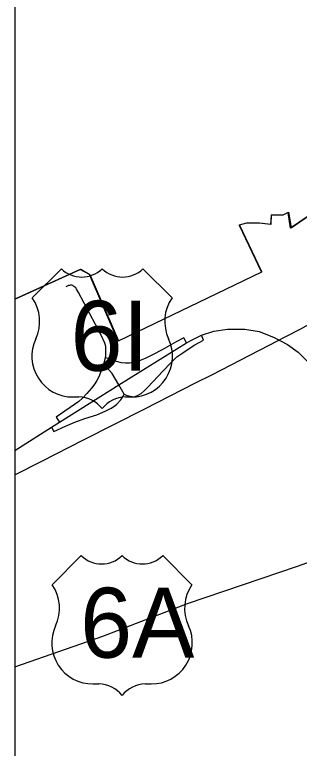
# Model space of a CAD drawing. Extents: x 0 to 96.2, y -27.5 to 31.3.
# Drawn here: x 43.823 to 44.361, y 17.525 to 18.907 of the extents above; entities that cross this region are included whole.
import ezdxf

# ---------------------------------------------------------------- set-up
doc = ezdxf.new("R2010")
doc.units = 0
for name, color, linetype in [('BOTTOM-BLKS', 7, 'Continuous'), ('TB1', 7, 'Continuous'), ('TB_PIPEMAT', 7, 'Continuous'), ('TB_PP_50x10_GRID', 7, 'Continuous'), ('TB_PROF_20x5_GRID', 7, 'Continuous'), ('TB_SIGN_XS', 7, 'Continuous'), ('TB_SUPER_50x0-5', 7, 'Continuous')]:
    doc.layers.add(name, color=color, linetype=linetype)

msp = doc.modelspace()

# ---------------------------------------------------------------- linework, layer by layer
at = {"layer": 'BOTTOM-BLKS'}
for points in [[(43.8234, 18.3711), (43.8234, 13.9869), (50.6234, 13.9869), (50.6234, 20.7869), (47.5697, 20.7869)], [(44.3788, 18.5289), (44.344, 18.5051), (44.3393, 18.5347), (44.3294, 18.5297), (44.3074, 18.5296), (44.3064, 18.5117), (44.2847, 18.5143), (44.2608, 18.5145), (44.2467, 18.5106), (44.2891, 18.4219), (44.0186, 18.2919), (43.9647, 18.4174), (43.9471, 18.4272), (43.8234, 18.3711)]]:
    msp.add_lwpolyline(points, dxfattribs=at)
at = {"layer": 'TB1'}
msp.add_line((43.8234, 20.7869), (43.8234, 13.9869), dxfattribs=at)
at = {"layer": 'TB_PIPEMAT'}
msp.add_lwpolyline([(43.8234, 18.3712), (43.948, 18.4277), (43.9655, 18.4179), (44.0195, 18.2924), (44.2899, 18.4224), (44.2476, 18.5111), (44.2616, 18.515), (44.2855, 18.5147), (44.3072, 18.5122), (44.3082, 18.5301), (44.3303, 18.5302), (44.3401, 18.5352), (44.3448, 18.5056), (44.3796, 18.5293)], dxfattribs=at)
at = {"layer": 'TB_PP_50x10_GRID'}
msp.add_lwpolyline([(43.8234, 18.04), (43.8748, 18.0658), (43.953, 18.1061), (44.0692, 18.1647), (44.1648, 18.2135), (44.1952, 18.2286), (44.3037, 18.2844), (44.3341, 18.2999), (44.3647, 18.3158), (44.3856, 18.3277), (44.4068, 18.3397), (44.4277, 18.3527), (44.4732, 18.3837), (44.554, 18.4402), (44.6783, 18.5278), (44.8269, 18.6306)], dxfattribs=at)
at = {"layer": 'TB_PROF_20x5_GRID'}
for points in [[(44.1476, 18.2887), (44.1423, 18.298), (44.1284, 18.2907), (44.1016, 18.2759), (44.0834, 18.2664), (44.0695, 18.2595), (44.0569, 18.2543), (44.0485, 18.2515), (44.0403, 18.2506), (44.0325, 18.2506), (44.0248, 18.2514), (44.0156, 18.2536), (43.9995, 18.259), (43.9945, 18.2608)], [(44.0299, 18.1922), (44.034, 18.1903), (44.0411, 18.1881), (44.0449, 18.1874), (44.0486, 18.1873), (44.0518, 18.188), (44.055, 18.1894), (44.0618, 18.1935), (44.068, 18.1986), (44.0751, 18.206), (44.1029, 18.2353), (44.1178, 18.2511), (44.1296, 18.2622), (44.1404, 18.2702), (44.1505, 18.2772), (44.1635, 18.2853), (44.1796, 18.2937), (44.176, 18.3034)], [(43.9916, 18.2486), (43.9894, 18.2431), (43.9819, 18.2249), (43.9787, 18.2179), (43.9748, 18.2115), (43.9685, 18.2032), (43.9594, 18.1931), (43.9512, 18.1848), (43.9443, 18.1782), (43.902, 18.1486), (43.9078, 18.1393)], [(43.8926, 18.1297), (43.8976, 18.1216), (43.919, 18.132), (43.9367, 18.1392), (43.9561, 18.1461), (43.9787, 18.153), (43.9944, 18.1598), (44.0053, 18.1655), (44.0108, 18.1689), (44.0155, 18.1729), (44.0235, 18.1815), (44.0284, 18.1882), (44.0299, 18.1922)]]:
    msp.add_lwpolyline(points, dxfattribs=at)
at = {"layer": 'TB_SIGN_XS'}
for points in [[(44.0308, 18.1906), (44.0299, 18.1922), (44.0197, 18.2098), (44.0071, 18.2308), (43.9916, 18.2486), (43.9945, 18.2608), (43.9951, 18.265), (43.9956, 18.2757), (43.9952, 18.2822), (43.9936, 18.2881), (43.9863, 18.3034), (43.944, 18.3836), (43.9402, 18.3902), (43.9386, 18.3922), (43.9369, 18.3939), (43.9352, 18.3953), (43.9332, 18.3966), (43.931, 18.3973), (43.9286, 18.3974), (43.9268, 18.3972), (43.925, 18.3966), (43.9202, 18.3946)], [(43.8234, 18.086), (43.8926, 18.1297), (43.9078, 18.1393), (44.0197, 18.2098), (44.1476, 18.2887), (44.1593, 18.2954), (44.176, 18.3034), (44.1995, 18.3107), (44.225, 18.3147), (44.2575, 18.3144), (44.285, 18.3099), (44.312, 18.2996), (44.3383, 18.2856), (44.3581, 18.271), (44.3771, 18.2523)], [(43.8234, 17.6782), (43.9898, 17.7357), (44.1497, 17.7978), (44.3569, 17.8681), (44.6417, 17.9697), (44.6431, 17.9702)]]:
    msp.add_lwpolyline(points, dxfattribs=at)
at = {"layer": 'TB_SUPER_50x0-5'}
for p, q in [((43.9116, 18.4285), (43.8567, 18.3736)), ((44.1204, 18.3736), (44.0655, 18.4285)), ((43.9336, 18.1868), (43.9446, 18.1868)), ((44.0325, 18.1868), (44.0435, 18.1868)), ((43.9491, 17.8877), (43.8942, 17.8327)), ((44.1579, 17.8327), (44.103, 17.8877)), ((43.9711, 17.646), (43.9821, 17.646)), ((44.07, 17.646), (44.081, 17.646))]:
    msp.add_line(p, q, dxfattribs=at)
for centre, radius, start, end in [((43.9501, 18.4677), 0.0549, 225.573, 314.427), ((44.027, 18.4677), 0.0549, 225.573, 314.427), ((43.7937, 18.3295), 0.0769, 334.5471, 35.0009), ((44.1834, 18.3295), 0.0769, 144.9991, 205.4529), ((43.9328, 18.2637), 0.0769, 154.8319, 270.6383), ((44.0443, 18.2637), 0.0769, 269.3617, 25.1681), ((43.9446, 18.1319), 0.0549, 36.8699, 90), ((44.0325, 18.1319), 0.0549, 90, 143.1301), ((43.9876, 17.9269), 0.0549, 225.573, 314.427), ((44.0645, 17.9269), 0.0549, 225.573, 314.427), ((43.8312, 17.7886), 0.0769, 334.5471, 35.0009), ((44.2209, 17.7886), 0.0769, 144.9991, 205.4529), ((43.9703, 17.7229), 0.0769, 154.8319, 270.6383), ((44.0818, 17.7229), 0.0769, 269.3617, 25.1681), ((43.9821, 17.591), 0.0549, 36.8699, 90), ((44.07, 17.591), 0.0549, 90, 143.1301)]:
    msp.add_arc(centre, radius, start, end, dxfattribs=at)

# ---------------------------------------------------------------- texts
for s, p in [('6I', (43.9289, 18.2362)), ('6A', (43.9469, 17.6954))]:
    msp.add_text(s, height=0.13184, dxfattribs=at).set_placement(p)

doc.saveas('drawing.dxf')
